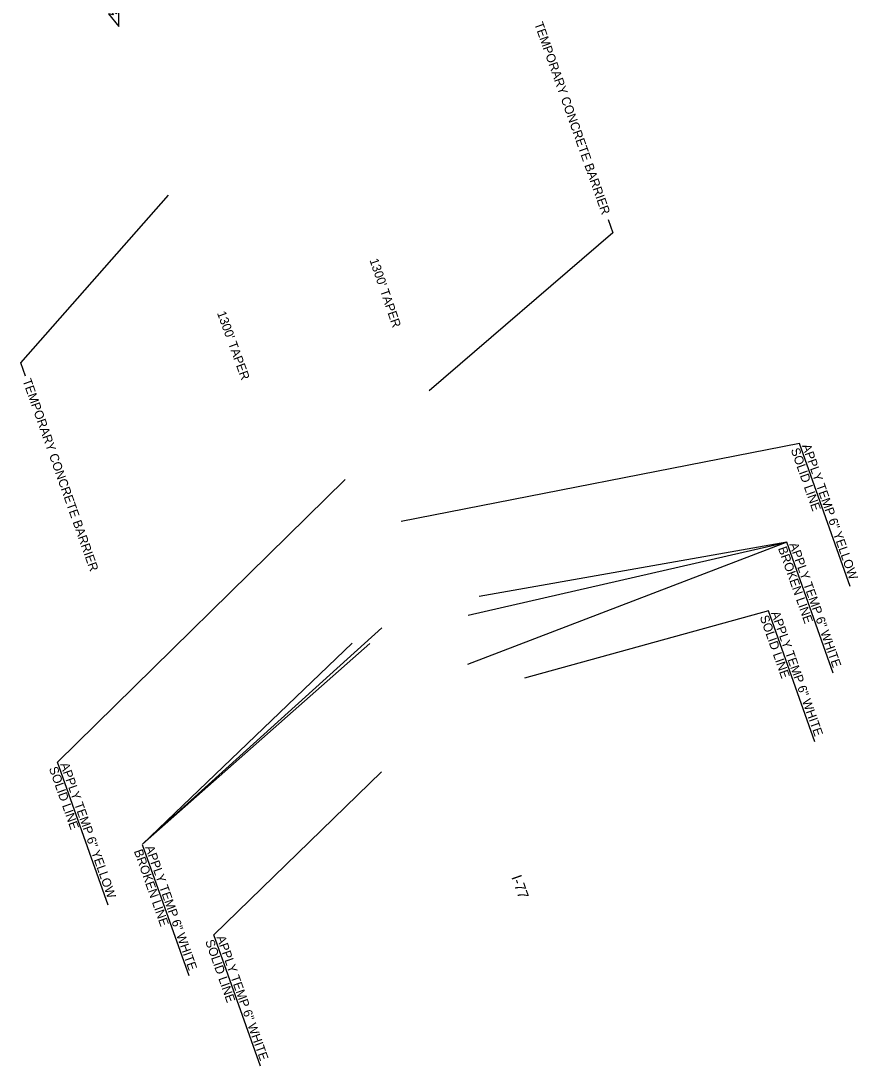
# Model space of a CAD drawing. Extents: x 2004770 to 2007199, y 1133765 to 1140032.
# Drawn here: x 2005086 to 2005645, y 1138449 to 1139147 of the extents above; entities that cross this region are included whole.
import ezdxf

# ---------------------------------------------------------------- set-up
doc = ezdxf.new("R2010")
doc.units = 0
doc.layers.add('RD_PD_MedBWall', color=7, linetype='Continuous')
doc.layers.add('RD_XS_Base', color=7, linetype='Continuous')

msp = doc.modelspace()

# ---------------------------------------------------------------- linework, layer by layer
at = {"layer": 'RD_PD_MedBWall'}
for p, q in [((2005640.09, 1138769.17), (2005606.26, 1138864.81)), ((2005597.74, 1138798.89), (2005384.52, 1138717.1)), ((2005384.85, 1138750.02), (2005597.74, 1138798.89)), ((2005628.73, 1138711.28), (2005597.74, 1138798.89)), ((2005616.54, 1138665.39), (2005585.54, 1138753)), ((2005167.24, 1138596.96), (2005307.47, 1138731.19)), ((2005167.24, 1138596.96), (2005319.2, 1138731.12)), ((2005144.45, 1138556.23), (2005110.62, 1138651.87)), ((2005198.38, 1138508.91), (2005167.39, 1138596.53)), ((2005246.04, 1138448.64), (2005215.04, 1138536.26))]:
    msp.add_line(p, q, dxfattribs=at)
msp.add_lwpolyline([(2005145.69, 1139162.62), (2005143.81, 1139161.93), (2005147.69, 1139151.28), (2005144.62, 1139151.94), (2005151.6, 1139143.48), (2005151.51, 1139154.45), (2005149.57, 1139151.97)], close=True, dxfattribs=at)
for points in [[(2005089.23, 1138909.76), (2005086.07, 1138918.71), (2005184.57, 1139030.67)], [(2005478.45, 1139014.42), (2005481.63, 1139005.43), (2005358.75, 1138899.89)], [(2005606.26, 1138864.81), (2005340.12, 1138812.52)], [(2005110.62, 1138651.87), (2005302.72, 1138840.65)], [(2005597.74, 1138798.89), (2005392.22, 1138762.41)], [(2005585.54, 1138753), (2005422.57, 1138707.89)], [(2005167.24, 1138596.96), (2005327.13, 1138741.49)], [(2005215.04, 1138536.26), (2005327.08, 1138645.2)]]:
    msp.add_lwpolyline(points, dxfattribs=at)

# ---------------------------------------------------------------- texts
for s, rotation, p in [('TEMPORARY CONCRETE BARRIER', 289.48201, (2005428.98, 1139145.28)), ("1300' TAPER", 288.95314, (2005318.87, 1138987.31)), ("1300' TAPER", 290.01088, (2005216.99, 1138951.98)), ('TEMPORARY CONCRETE BARRIER', 289.48201, (2005087.07, 1138906.87)), ('APPLY TEMP 6" YELLOW', 289.48201, (2005607.87, 1138863.26)), ('SOLID LINE', 289.48201, (2005600.33, 1138860.59)), ('BROKEN LINE', 289.48201, (2005591.8, 1138794.67)), ('APPLY TEMP 6" WHITE', 289.48201, (2005599.35, 1138797.34)), ('APPLY TEMP 6" WHITE', 289.48201, (2005587.15, 1138751.45)), ('SOLID LINE', 289.48201, (2005579.61, 1138748.78)), ('SOLID LINE', 289.48201, (2005104.69, 1138647.65)), ('APPLY TEMP 6" YELLOW', 289.48201, (2005112.23, 1138650.32)), ('BROKEN LINE', 289.48201, (2005161.46, 1138592.31)), ('APPLY TEMP 6" WHITE', 289.48201, (2005169, 1138594.97)), ('APPLY TEMP 6" WHITE', 289.48201, (2005216.65, 1138534.71)), ('SOLID LINE', 289.48201, (2005209.11, 1138532.04))]:
    msp.add_text(s, height=6, rotation=rotation, dxfattribs=at).set_placement(p)
at = {"layer": 'RD_XS_Base'}
msp.add_text('I-77', height=7, rotation=289.48201, dxfattribs=at).set_placement((2005413.61, 1138574.91))

doc.saveas('drawing.dxf')
